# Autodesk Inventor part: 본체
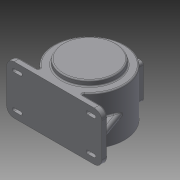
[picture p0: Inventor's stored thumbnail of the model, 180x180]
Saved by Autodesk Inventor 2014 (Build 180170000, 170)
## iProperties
Created: 2015-06
Part Number: 본체
Material: Generic
Document SubType Name: Modeling
Designer: user
Density: 1 g/cm^3
Appearance: Default
Author: user
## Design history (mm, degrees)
sketch "Sketch1"
  geometry: L1 (-115, -59)-(115, -59); L2 (115, -59)-(115, 59); L3 (115, 59)-(-115, 59); L4 (-115, 59)-(-115, -59); L5 (-115, -59)-(115, 59); L6 (115, -59)-(-115, 59); 1 further point
  constraints: 12 end point, 2 midpoint, 2 parallel, 1 horizontal, 1 perpendicular
  dimensions: "d0" = 230 distance of L2.end L3.end; "d1" = 118 distance of L1.end L2.end
extrude "Extrusion1" new body sketch "Sketch1" distance "d2" = 14; taper "d3" = 0 deg
sketch "Sketch2"
  geometry: L1 (115, 59)-(-115, 59) reference; L2 (-97, -41)-(97, -41); L3 (97, -41)-(97, 41); L4 (97, 41)-(-97, 41); L5 (-97, 41)-(-97, -41); L6 (-97, -41)-(97, 41); L7 (97, -41)-(-97, 41); L8 (-97, 41)-(-81, 41); L9 (-97, 37)-(-81, 37); L10 (-81, 45)-(-97, 45); L11 (-97, -41)-(-81, -41); L12 (-97, -37)-(-81, -37); L13 (-81, -45)-(-97, -45); L14 (-81, 32)-(-97, 32); L15 (-97, 50)-(-81, 50); L16 (-81, -32)-(-97, -32); L17 (-97, -50)-(-81, -50); A1 r 4 centre (-97, 41) between (-97, 45) and (-97, 37); A2 r 4 centre (-81, 41) between (-81, 37) and (-81, 45); A3 r 4 centre (-97, -41) between (-97, -37) and (-97, -45); A4 r 4 centre (-81, -41) between (-81, -45) and (-81, -37); A5 r 9 centre (-97, 41) between (-97, 50) and (-97, 32); A6 r 9 centre (-81, 41) between (-81, 32) and (-81, 50); A7 r 9 centre (-97, -41) between (-97, -32) and (-97, -50); A8 r 9 centre (-81, -41) between (-81, -50) and (-81, -32); 5 further points
  constraints: 36 end point, 16 point on circle, 8 centre point, 8 parallel, 8 tangent, 5 midpoint, 1 coincident, 1 horizontal, 1 perpendicular, 6 other
  dimensions: "d4" = 194 distance of L3.end L4.end; "d5" = 82 distance of L2.end L3.end; "d8" = 16 distance of L4.end L8.end; "d9" = 8 distance between parallel lines of L9 L10; "d10" = 16 distance of L11.end L2.start; "d11" = 8 distance between parallel lines of L13 L12; "d12" = 5 distance between parallel lines of L15 L10; "d13" = 5 distance between parallel lines of L16 L12
extrude "Extrusion2" join sketch "Sketch2" distance "d14" = 3; taper "d15" = 0 deg
extrude "Extrusion3" cut sketch "Sketch2" stored distance "d16" = 3; taper "d17" = 0 deg
mirror "Mirror1"
fillet "Fillet1" dims "d18" = 18
fillet "Fillet2" dims "d19" = 3
sketch "Sketch3"
  geometry: L1 (0, 0)-(0, 85); C1 r 85 at (0, 85)
  constraints: 2 end point, 1 centre point, 1 coincident, 1 vertical
  dimensions: "d20" = 85 distance of L1.start L1.end; "d21" = 170 diameter of C1
extrude "Extrusion4" join sketch "Sketch3" stored distance "d22" = 118; taper "d23" = 0 deg
workplane "Work Plane1"
sketch "Sketch4"
  geometry: L1 (97, 0)-(97, 85); C1 r 65 at (97, 85)
  constraints: 2 end point, 1 centre point, 1 coincident, 1 vertical
  dimensions: "d25" = 85 distance of L1.start L1.end; "d26" = 130 diameter of C1
extrude "Extrusion5" join sketch "Sketch4" distance "d27" = 134; taper "d28" = 0 deg
sketch "Sketch5"
  geometry: L1 (0, -85)-(0, 0); C1 r 47.5 at (0, 0)
  constraints: 2 end point, 1 centre point, 1 coincident, 1 vertical
  dimensions: "d29" = 85 distance of L1.start L1.end; "d30" = 95 diameter of C1
extrude "Extrusion6" cut sketch "Sketch5" distance "d31" = 11; taper "d32" = 0 deg
sketch "Sketch6"
  geometry: L1 (0, -85)-(0, 0); C1 r 77 at (0, 0)
  constraints: 2 end point, 1 centre point, 1 coincident, 1 vertical
  dimensions: "d33" = 85 distance of L1.start L1.end; "d34" = 154 diameter of C1
extrude "Extrusion7" cut sketch "Sketch6" distance "d35" = 102; taper "d36" = 0 deg
sketch "Sketch7"
  geometry: L1 (0, -85)-(0, 0); C1 r 77 at (0, 0) reference; C2 r 23.5 at (0, 0)
  constraints: 2 end point, 1 centre point, 1 coincident, 1 vertical
  dimensions: "d37" = 85 distance of L1.start L1.end (derived); "d38" = 47 diameter of C2
extrude "Extrusion8" cut sketch "Sketch7" distance "d39" = 14; taper "d40" = 0 deg
sketch "Sketch8"
  geometry: L1 (0, -85)-(0, 0); C1 r 23.5 at (0, 0) reference; C2 r 15 at (0, 0)
  constraints: 2 end point, 1 centre point, 1 coincident, 1 vertical
  dimensions: "d41" = 85 distance of L1.start L1.end (derived); "d42" = 30 diameter of C2
extrude "Extrusion9" cut sketch "Sketch8" distance "d43" = 3; taper "d44" = 0 deg
sketch "Sketch9"
  geometry: L1 (0, -85)-(0, 0); C1 r 23.5 at (0, 0) reference; C2 r 77 at (0, 0) reference; C3 r 31 at (0, 0)
  constraints: 2 end point, 1 centre point, 1 coincident, 1 vertical
  dimensions: "d45" = 85 distance of L1.start L1.end (derived); "d46" = 62 diameter of C3
extrude "Extrusion10" join sketch "Sketch9" distance "d47" = 3.5; taper "d48" = 0 deg
chamfer "Chamfer1" distance "d49" = 3.5; stored, may be unused: second distance "d50" = 2, angle "d51" = 25 deg
sketch "Sketch10"
  geometry: L1 (84.87, 80.297)-(109, 14); L2 (97, 14)-(46.733, 14) reference; L3 (-46.733, 14)-(-97, 14) reference; L4 (109, 14)-(97, 14) reference; L5 (-97, 14)-(-109, 14) reference; L6 (115, 14)-(115, 0) reference; L7 (0, 0)-(115, 0); A1 r 85 centre (0, 85) between (46.733, 14) and (-46.733, 14) reference
  constraints: 4 end point, 1 perpendicular, 1 point on circle, 1 point on line
  dimensions: "d52" = 6 distance from line of L6 L1.end; "d54" = 110 deg angle of L4 L1
feature "Rib1" sketch "Sketch10" dims "d55" = 1, "d56" = 15, "d57" = 0, "d58" = 0, "d59" = 1, "d60" = 1
mirror "Mirror2"
workplane "Work Plane2"
sketch "Sketch11"
  geometry: L1 (42.5, -42.5)-(-42.5, -42.5); L2 (-42.5, -42.5)-(-42.5, 42.5); L3 (-42.5, 42.5)-(42.5, 42.5); L4 (42.5, 42.5)-(42.5, -42.5); L5 (42.5, -42.5)-(-42.5, 42.5); L6 (-42.5, -42.5)-(42.5, 42.5); 1 further point
  constraints: 12 end point, 2 midpoint, 2 parallel, 1 horizontal, 1 perpendicular
  dimensions: "d62" = 85 distance of L2.end L3.end; "d63" = 85 distance of L1.end L2.end
extrude "Extrusion11" join sketch "Sketch11" stored distance "d64" = 3.5; taper "d65" = 0 deg
sketch "Sketch12"
  geometry: C1 r 35 at (0, 0); 1 further point
  constraints: 1 centre point, 1 coincident
  dimensions: "d66" = 70 diameter of C1
extrude "Extrusion12" cut sketch "Sketch12" stored distance "d67" = 3.5; taper "d68" = 0 deg
sketch "Sketch13"
  geometry: L1 (-35.5, -35.5)-(35.5, -35.5); L2 (35.5, -35.5)-(35.5, 35.5); L3 (35.5, 35.5)-(-35.5, 35.5); L4 (-35.5, 35.5)-(-35.5, -35.5); L5 (-35.5, -35.5)-(35.5, 35.5); L6 (35.5, -35.5)-(-35.5, 35.5); C1 r 35 at (0, 0) reference; 4 further points
  constraints: 12 end point, 4 coincident, 2 midpoint, 2 parallel, 1 horizontal, 1 perpendicular
  dimensions: "d69" = 71 distance of L3.end L2.end; "d70" = 71 distance of L2.end L1.end
hole "Hole1" sketch "Sketch13" at (-35.5, 35.5), (35.5, 35.5), (35.5, -35.5), (-35.5, -35.5) diameter "d71" = 3.242; stored, may be unused: countersink angle "d75" = 90 deg, drill point angle "d77" = 118 deg; dims "d72" = 10, "d73" = 4, "d74" = 2, "d76" = 13
sketch "Sketch14" dims "d78" = 110
  geometry: L1 (0, -85)-(0, 0); C1 r 65 at (0, 0) reference; 2 further points
  constraints: 2 end point, 1 coincident, 1 point on line, 1 vertical, 1 vertical alignment, 2 other
hole "Hole2" sketch "Sketch14" at (0, -55) diameter "d79" = 3.242; stored, may be unused: countersink angle "d83" = 90 deg, drill point angle "d85" = 118 deg; dims "d80" = 10, "d81" = 4, "d82" = 2, "d84" = 38
pattern_circular "Circular Pattern1" dims angle "d87" = 360 deg
fillet "Fillet3" dims "d89" = 3
chamfer "Chamfer2" distance "d90" = 1; stored, may be unused: second distance "d91" = 2, angle "d92" = 25 deg
fillet "Fillet4" dims "d93" = 3
chamfer "Chamfer3" distance "d94" = 1; stored, may be unused: second distance "d95" = 2, angle "d96" = 25 deg
fillet "Fillet5" dims "d97" = 7.5
fillet "Fillet6" dims "d98" = 7
fillet "Fillet7" dims "d99" = 3
fillet "Fillet8" dims "d100" = 3
chamfer "Chamfer4" distance "d101" = 1; stored, may be unused: second distance "d102" = 2, angle "d103" = 25 deg
body "Solid1"
other parameters: "d24" = 13, "d61" = -173
